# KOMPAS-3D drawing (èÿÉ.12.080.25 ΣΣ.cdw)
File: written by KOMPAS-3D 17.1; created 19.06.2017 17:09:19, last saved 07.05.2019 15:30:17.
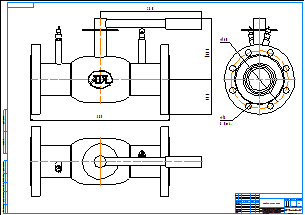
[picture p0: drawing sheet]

Sheet 1: A1, landscape

Title block, sheet 1: name: КШР.12.080.25 фф; material: Внимание! Данный продукт является объектом авторского права ООО «Торговый Дом АДЛ». / Запрещается изменение, копирование, распространение / (в том числе путем копирования на другие сайты и ресурсы в Интернете) / или любое иное использование информации и объектов без предварительного / согласия правообладателя (ООО «Торговый Дом АДЛ»).; scale: 1:1; sheets: 1; organisation: ООО "Торговый дом АДЛ"; sheet format: A1; stored path: C:\Users\tra\Desktop\2д чертежи\Шаровые краны БИВАЛ\КШР_Бивал_серия_12\KOMPAS 2D\КШР.12.080.25 фф.cdw

Views: Спереди 1, Проекционный вид 2, Проекционный вид 3
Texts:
  Klimkovich
  ADL
Dimensions and other numbers on the sheet: 385; 280; 168,8; 97,5; 160; 18; 8 Отв.; 1:1; 1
